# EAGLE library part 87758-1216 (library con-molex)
12 Pin - 2mm Dual Row Single Wafer, Vertical T/H HDR Source: http://www.molex.com/pdm_docs/sd/877580616_sd.pdf
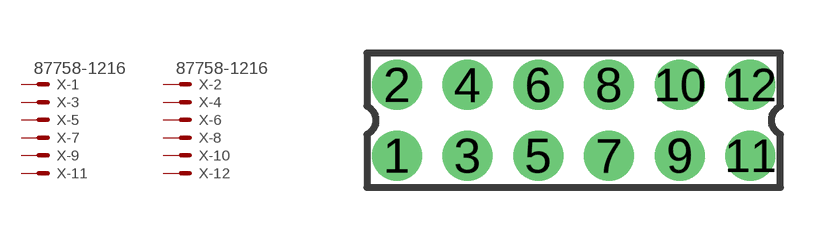
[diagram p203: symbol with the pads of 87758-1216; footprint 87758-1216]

Designator prefix X; gates -1=MV -2=MV -3=M -4=M -5=M -6=M -7=M -8=M -9=M -10=M -11=M -12=M

## 87758-1216 (MPN: 87758-1216; OC_FARNELL: unknown; OC_NEWARK: 25M5671)  [87758-1216]
1  -1:S  pas
2  -2:S  pas
3  -3:S  pas
4  -4:S  pas
5  -5:S  pas
6  -6:S  pas
7  -7:S  pas
8  -8:S  pas
9  -9:S  pas
10  -10:S  pas
11  -11:S  pas
12  -12:S  pas

## Footprint 87758-1216 (pad centres in mm)
12 Pin - 2mm Dual Row Single Wafer, Vertical T/H HDR Source: http://www.molex.com/pdm_docs/sd/877580616_sd.pdf
drill 0.9 pad 1.27 round: 1 -5,-1; 2 -5,1; 3 -3,-1; 4 -3,1; 5 -1,-1; 6 -1,1; 7 1,-1; 8 1,1; 9 3,-1; 10 3,1; 11 5,-1; 12 5,1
